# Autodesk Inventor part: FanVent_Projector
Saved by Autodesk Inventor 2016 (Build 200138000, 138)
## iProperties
Created: 2016-03
Part Number: FanVent_Projector
Material: Generic
Document SubType Name: Modeling
Designer: bongo_000
Density: 1 g/cm^3
Appearance: Default
Author: bongo_000
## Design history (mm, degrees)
feature "Base1"
body "Solid1"
